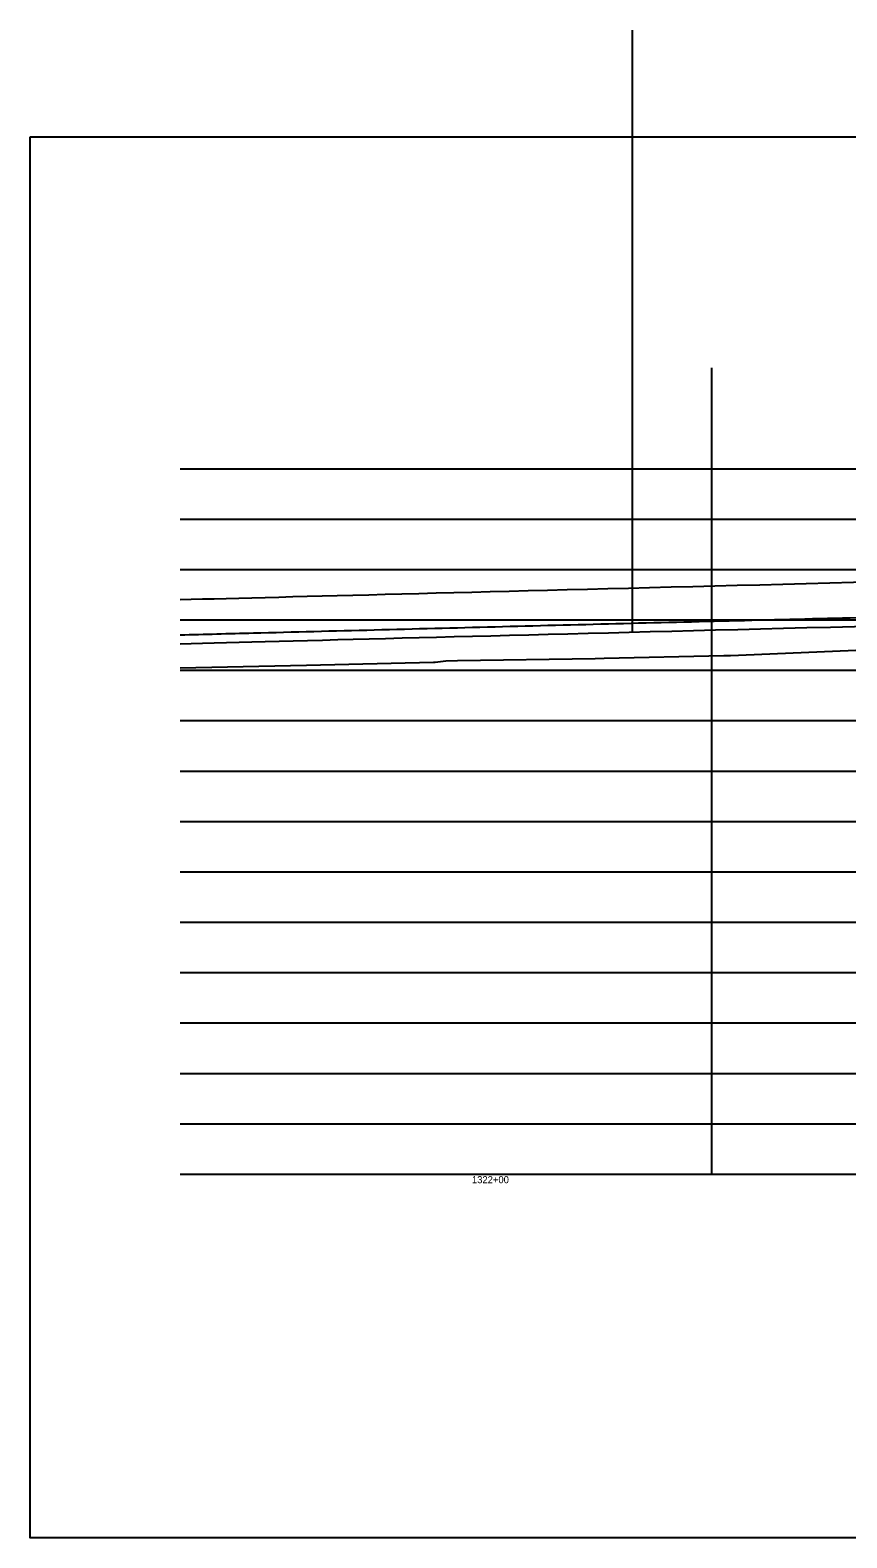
# Model space of a CAD drawing. Extents: x 680639 to 702326, y 743523 to 756592.
# Drawn here: x 688358.1 to 688439.1, y 751717.1 to 751866.7 of the extents above; entities that cross this region are included whole.
import ezdxf

# ---------------------------------------------------------------- set-up
doc = ezdxf.new("R2010")
doc.units = 0
for name, color, linetype in [('B_Concrete', 7, 'Continuous'), ('B_Proposed Ground', 7, 'Continuous'), ('R_Axis', 7, 'Continuous'), ('R_Axis Annot', 7, 'Continuous'), ('R_Exist Surface', 7, 'Continuous'), ('R_Vert Alg', 7, 'Continuous')]:
    doc.layers.add(name, color=color, linetype=linetype)

msp = doc.modelspace()

# ---------------------------------------------------------------- linework, layer by layer
at = {"layer": 'B_Concrete'}
msp.add_open_spline([(688372.96, 751810.2), (688384.35, 751810.5), (688420.74, 751811.44), (688507.13, 751813.6), (688632.13, 751816.46), (688757.14, 751819), (688844.65, 751820.6), (688882.16, 751821.24), (688897.6, 751821.51), (688900.54, 751821.56), (688903.48, 751821.61)], degree=3, dxfattribs=at)
at = {"layer": 'B_Proposed Ground'}
msp.add_line((688417.84, 751866.7), (688417.84, 751806.98), dxfattribs=at)
msp.add_open_spline([(688372.96, 751805.82), (688384.39, 751806.12), (688420.81, 751807.06), (688507.23, 751809.22), (688632.23, 751812.08), (688757.23, 751814.62), (688844.73, 751816.22), (688882.24, 751816.87), (688897.65, 751817.13), (688900.57, 751817.18), (688903.48, 751817.23)], degree=3, dxfattribs=at)
at = {"layer": 'R_Axis'}
for p, q in [((688425.74, 751753.19), (688425.74, 751833.19)), ((688372.96, 751823.19), (688903.48, 751823.19)), ((688372.96, 751818.19), (688903.48, 751818.19)), ((688372.96, 751813.19), (688903.48, 751813.19)), ((688372.96, 751808.19), (688903.48, 751808.19)), ((688372.96, 751803.19), (688903.48, 751803.19)), ((688372.96, 751798.19), (688903.48, 751798.19)), ((688372.96, 751793.19), (688903.48, 751793.19)), ((688372.96, 751788.19), (688903.48, 751788.19)), ((688372.96, 751783.19), (688903.48, 751783.19)), ((688372.96, 751778.19), (688903.48, 751778.19)), ((688372.96, 751773.19), (688903.48, 751773.19)), ((688372.96, 751768.19), (688903.48, 751768.19)), ((688372.96, 751763.19), (688903.48, 751763.19)), ((688372.96, 751758.19), (688903.48, 751758.19)), ((688372.96, 751753.19), (688903.48, 751753.19))]:
    msp.add_line(p, q, dxfattribs=at)
at = {"layer": 'R_Exist Surface'}
msp.add_lwpolyline([(688358.07, 751856.12), (688913.85, 751856.12), (688913.85, 751717.1), (688358.07, 751717.1)], close=True, dxfattribs=at)
msp.add_lwpolyline([(688372.96, 751803.44), (688383.92, 751803.66), (688385.52, 751803.7), (688398.12, 751803.99), (688398.27, 751803.99), (688399.33, 751804.12), (688400.5, 751804.16), (688414.17, 751804.37), (688415.06, 751804.4), (688426.92, 751804.65), (688427.61, 751804.66), (688442.4, 751805.27)], dxfattribs=at)
at = {"layer": 'R_Vert Alg'}
msp.add_spline([(688372.96, 751806.7), (688380.23, 751806.89), (688392.23, 751807.2), (688404.23, 751807.51), (688416.23, 751807.82), (688428.23, 751808.12), (688440.23, 751808.42), (688452.23, 751808.72), (688464.23, 751809.02), (688476.23, 751809.31), (688488.23, 751809.6), (688500.23, 751809.89), (688512.23, 751810.18), (688524.23, 751810.46), (688536.23, 751810.74), (688548.23, 751811.02), (688560.23, 751811.3), (688572.23, 751811.57), (688584.23, 751811.84), (688596.23, 751812.11), (688608.23, 751812.37), (688620.23, 751812.64), (688632.23, 751812.9), (688644.23, 751813.15), (688656.23, 751813.41), (688668.23, 751813.66), (688680.23, 751813.91), (688692.23, 751814.16), (688704.23, 751814.41), (688716.23, 751814.65), (688728.23, 751814.89), (688740.23, 751815.13), (688752.23, 751815.36), (688764.23, 751815.59), (688776.23, 751815.82), (688788.23, 751816.05), (688800.23, 751816.28), (688812.23, 751816.5), (688824.23, 751816.72), (688836.23, 751816.93), (688848.23, 751817.15), (688860.23, 751817.36), (688872.23, 751817.57), (688884.23, 751817.78), (688896.23, 751817.98), (688903.48, 751818.11)], degree=3, dxfattribs=at)

# ---------------------------------------------------------------- texts
at = {"layer": 'R_Axis Annot'}
msp.add_text('1322+00', height=0.7, dxfattribs=at).set_placement((688401.93, 751752.29))

doc.saveas('drawing.dxf')
